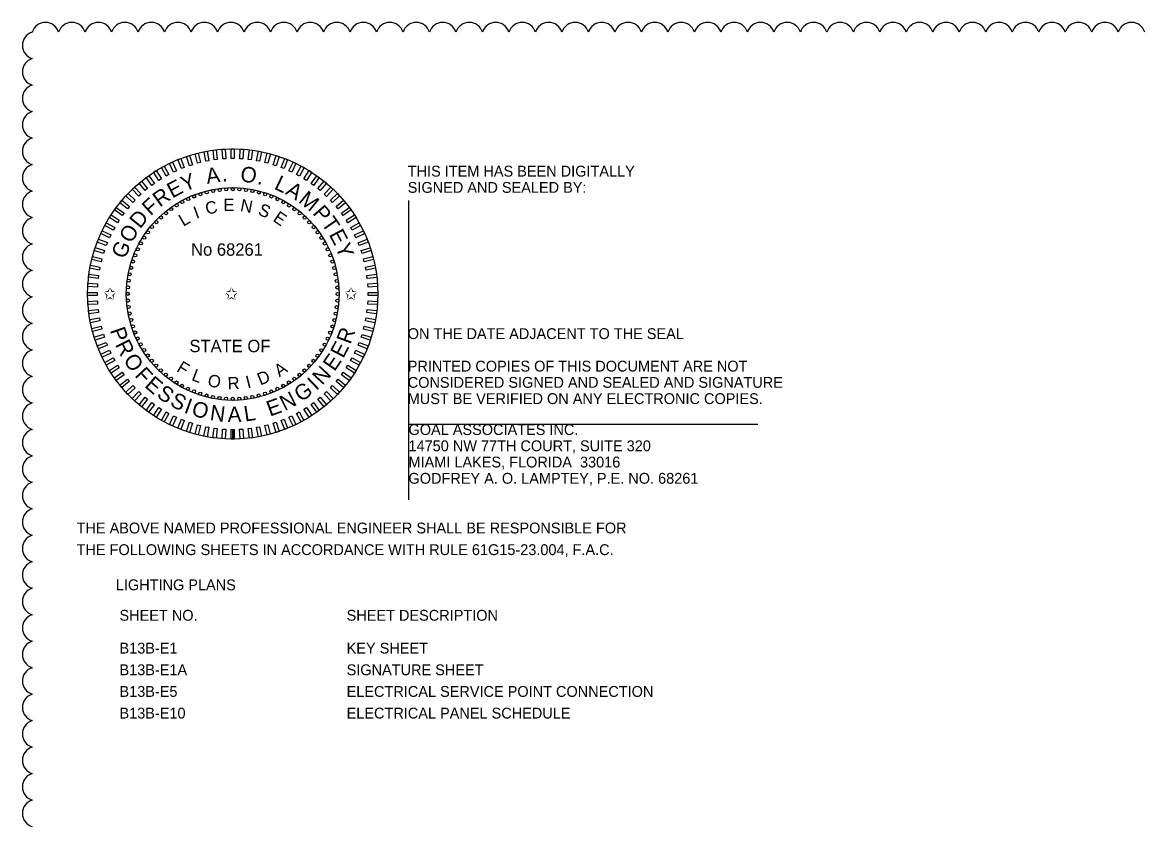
# Model space of a CAD drawing. Extents: x -811.3 to -795.2, y -2199.5 to -2188.9.
# Drawn here: x -810.85 to -803.6, y -2194.13 to -2188.94 of the extents above; entities that cross this region are included whole.
import ezdxf

# ---------------------------------------------------------------- set-up
doc = ezdxf.new("R2010")
doc.units = 0
for name, color, linetype in [('PlotBorder_dp', 7, 'Continuous'), ('ScratchEle_dp', 7, 'Continuous'), ('SheetBorder_dp', 7, 'Continuous'), ('SheetLines_dp', 7, 'Continuous'), ('TextMinor', 7, 'Continuous'), ('TextMisc', 7, 'Continuous')]:
    doc.layers.add(name, color=color, linetype=linetype)

msp = doc.modelspace()

# ---------------------------------------------------------------- linework, layer by layer
at = {"layer": 'PlotBorder_dp'}
for p, q in [((-809.5001, -2191.6301), (-809.5003, -2191.5676)), ((-809.4901, -2191.6301), (-809.4903, -2191.5676)), ((-809.4801, -2191.6301), (-809.4803, -2191.5676))]:
    msp.add_line(p, q, dxfattribs=at)
for points in [[(-809.7508, -2189.8572), (-809.77, -2189.8635), (-809.7893, -2189.8041), (-809.7701, -2189.7979)], [(-809.6979, -2189.8425), (-809.7174, -2189.8475), (-809.7329, -2189.7871), (-809.7134, -2189.782)], [(-809.6441, -2189.8312), (-809.6639, -2189.8349), (-809.6756, -2189.7736), (-809.6558, -2189.7698)], [(-809.5897, -2189.8232), (-809.6097, -2189.8257), (-809.6175, -2189.7638), (-809.5975, -2189.7612)], [(-809.5349, -2189.8187), (-809.555, -2189.8199), (-809.559, -2189.7576), (-809.5388, -2189.7563)], [(-809.4799, -2189.8176), (-809.5001, -2189.8176), (-809.5001, -2189.7551), (-809.4799, -2189.7551)], [(-809.425, -2189.8199), (-809.4452, -2189.8187), (-809.4412, -2189.7563), (-809.4211, -2189.7576)], [(-809.3703, -2189.8257), (-809.3904, -2189.8232), (-809.3825, -2189.7613), (-809.3625, -2189.7638)], [(-809.3162, -2189.835), (-809.336, -2189.8312), (-809.3243, -2189.7699), (-809.3045, -2189.7736)], [(-809.2626, -2189.8476), (-809.2822, -2189.8426), (-809.2667, -2189.7821), (-809.2471, -2189.7871)], [(-809.21, -2189.8635), (-809.2292, -2189.8573), (-809.2099, -2189.7979), (-809.1907, -2189.8042)], [(-809.9027, -2189.9209), (-809.9204, -2189.9306), (-809.9505, -2189.8759), (-809.9328, -2189.8662)], [(-809.8535, -2189.8965), (-809.8717, -2189.9051), (-809.8983, -2189.8486), (-809.8801, -2189.84)], [(-809.8028, -2189.8753), (-809.8215, -2189.8827), (-809.8445, -2189.8246), (-809.8258, -2189.8172)], [(-809.1585, -2189.8828), (-809.1773, -2189.8753), (-809.1543, -2189.8173), (-809.1355, -2189.8247)], [(-809.1083, -2189.9052), (-809.1266, -2189.8966), (-809.1, -2189.8401), (-809.0817, -2189.8487)], [(-809.0596, -2189.9307), (-809.0773, -2189.921), (-809.0473, -2189.8663), (-809.0296, -2189.876)], [(-809.9962, -2189.9787), (-810.0125, -2189.9906), (-810.0492, -2189.94), (-810.0329, -2189.9282)], [(-809.9504, -2189.9483), (-809.9674, -2189.9591), (-810.0009, -2189.9064), (-809.9838, -2189.8956)], [(-809.0127, -2189.9592), (-809.0297, -2189.9484), (-808.9962, -2189.8957), (-808.9792, -2189.9065)], [(-808.9676, -2189.9907), (-808.9839, -2189.9788), (-808.9472, -2189.9283), (-808.9308, -2189.9402)], [(-810.0817, -2190.0478), (-810.0964, -2190.0616), (-810.1392, -2190.0161), (-810.1244, -2190.0022)], [(-810.04, -2190.0119), (-810.0556, -2190.0247), (-810.0954, -2189.9766), (-810.0798, -2189.9638)], [(-808.9245, -2190.0249), (-808.9401, -2190.012), (-808.9003, -2189.9639), (-808.8847, -2189.9768)], [(-808.8837, -2190.0617), (-808.8984, -2190.0479), (-808.8557, -2190.0024), (-808.841, -2190.0162)], [(-810.1579, -2190.127), (-810.1707, -2190.1425), (-810.2188, -2190.1027), (-810.206, -2190.0872)], [(-810.121, -2190.0862), (-810.1348, -2190.1009), (-810.1804, -2190.0581), (-810.1665, -2190.0434)], [(-808.8453, -2190.101), (-808.8591, -2190.0863), (-808.8136, -2190.0436), (-808.7998, -2190.0583)], [(-808.8094, -2190.1427), (-808.8223, -2190.1271), (-808.7742, -2190.0873), (-808.7613, -2190.1029)], [(-810.192, -2190.17), (-810.2039, -2190.1864), (-810.2544, -2190.1497), (-810.2426, -2190.1333)], [(-808.7762, -2190.1865), (-808.7881, -2190.1702), (-808.7376, -2190.1335), (-808.7257, -2190.1498)], [(-810.252, -2190.2621), (-810.2617, -2190.2798), (-810.3164, -2190.2497), (-810.3067, -2190.232)], [(-810.2235, -2190.2151), (-810.2343, -2190.2322), (-810.287, -2190.1987), (-810.2762, -2190.1817)], [(-808.7459, -2190.2323), (-808.7567, -2190.2153), (-808.7039, -2190.1818), (-808.6931, -2190.1989)], [(-808.7184, -2190.28), (-808.7281, -2190.2623), (-808.6734, -2190.2322), (-808.6637, -2190.2499)], [(-810.2775, -2190.3108), (-810.2861, -2190.3291), (-810.3426, -2190.3025), (-810.334, -2190.2842)], [(-808.694, -2190.3292), (-808.7026, -2190.311), (-808.6461, -2190.2844), (-808.6375, -2190.3027)], [(-810.3, -2190.361), (-810.3074, -2190.3798), (-810.3654, -2190.3568), (-810.358, -2190.338)], [(-808.6728, -2190.3799), (-808.6802, -2190.3612), (-808.6222, -2190.3382), (-808.6147, -2190.357)], [(-810.3351, -2190.4651), (-810.3401, -2190.4847), (-810.4006, -2190.4691), (-810.3956, -2190.4496)], [(-810.3192, -2190.4125), (-810.3254, -2190.4317), (-810.3848, -2190.4124), (-810.3786, -2190.3932)], [(-808.6548, -2190.4319), (-808.661, -2190.4127), (-808.6016, -2190.3934), (-808.5954, -2190.4126)], [(-808.64, -2190.4849), (-808.6451, -2190.4653), (-808.5846, -2190.4498), (-808.5796, -2190.4693)], [(-810.3477, -2190.5186), (-810.3515, -2190.5385), (-810.4129, -2190.5268), (-810.4091, -2190.5069)], [(-808.6287, -2190.5386), (-808.6325, -2190.5188), (-808.5711, -2190.5071), (-808.5673, -2190.5269)], [(-810.357, -2190.5728), (-810.3595, -2190.5928), (-810.4215, -2190.585), (-810.4189, -2190.565)], [(-808.6207, -2190.593), (-808.6232, -2190.573), (-808.5613, -2190.5652), (-808.5588, -2190.5852)], [(-810.3628, -2190.6275), (-810.3641, -2190.6476), (-810.4264, -2190.6437), (-810.4251, -2190.6236)], [(-808.6162, -2190.6478), (-808.6174, -2190.6277), (-808.5551, -2190.6238), (-808.5539, -2190.6439)], [(-810.3652, -2190.6824), (-810.3652, -2190.7026), (-810.4276, -2190.7026), (-810.4276, -2190.6824)], [(-810.3641, -2190.7374), (-810.3628, -2190.7575), (-810.4251, -2190.7614), (-810.4264, -2190.7413)], [(-808.6175, -2190.7577), (-808.6162, -2190.7376), (-808.5539, -2190.7415), (-808.5551, -2190.7616)], [(-808.6151, -2190.7028), (-808.6151, -2190.6826), (-808.5527, -2190.6826), (-808.5527, -2190.7028)], [(-810.3595, -2190.7922), (-810.357, -2190.8122), (-810.4189, -2190.82), (-810.4215, -2190.8)], [(-808.6233, -2190.8124), (-808.6207, -2190.7923), (-808.5588, -2190.8002), (-808.5613, -2190.8202)], [(-810.3516, -2190.8466), (-810.3478, -2190.8664), (-810.4091, -2190.8781), (-810.4129, -2190.8583)], [(-808.6325, -2190.8666), (-808.6287, -2190.8467), (-808.5674, -2190.8584), (-808.5712, -2190.8783)], [(-810.3402, -2190.9003), (-810.3352, -2190.9199), (-810.3957, -2190.9354), (-810.4007, -2190.9159)], [(-810.3255, -2190.9533), (-810.3192, -2190.9725), (-810.3786, -2190.9918), (-810.3849, -2190.9726)], [(-808.6611, -2190.9727), (-808.6548, -2190.9535), (-808.5954, -2190.9728), (-808.6017, -2190.992)], [(-808.6451, -2190.9201), (-808.6401, -2190.9005), (-808.5796, -2190.916), (-808.5846, -2190.9356)], [(-810.3075, -2191.0052), (-810.3, -2191.024), (-810.3581, -2191.047), (-810.3655, -2191.0282)], [(-808.6803, -2191.0242), (-808.6729, -2191.0054), (-808.6148, -2191.0284), (-808.6222, -2191.0472)], [(-810.2862, -2191.0559), (-810.2776, -2191.0742), (-810.3341, -2191.1008), (-810.3427, -2191.0825)], [(-810.2618, -2191.1052), (-810.2521, -2191.1229), (-810.3068, -2191.153), (-810.3165, -2191.1353)], [(-808.7282, -2191.1231), (-808.7185, -2191.1054), (-808.6638, -2191.1355), (-808.6735, -2191.1532)], [(-808.7027, -2191.0744), (-808.6941, -2191.0561), (-808.6376, -2191.0827), (-808.6462, -2191.101)], [(-810.2344, -2191.1529), (-810.2236, -2191.1699), (-810.2763, -2191.2034), (-810.2871, -2191.1863)], [(-808.7568, -2191.1701), (-808.746, -2191.153), (-808.6932, -2191.1865), (-808.704, -2191.2035)], [(-810.204, -2191.1987), (-810.1922, -2191.215), (-810.2427, -2191.2517), (-810.2545, -2191.2354)], [(-810.1708, -2191.2425), (-810.158, -2191.2581), (-810.2061, -2191.2979), (-810.2189, -2191.2823)], [(-808.8224, -2191.2582), (-808.8095, -2191.2427), (-808.7614, -2191.2825), (-808.7743, -2191.298)], [(-808.7882, -2191.2152), (-808.7763, -2191.1988), (-808.7258, -2191.2355), (-808.7377, -2191.2519)], [(-810.135, -2191.2842), (-810.1211, -2191.2989), (-810.1667, -2191.3416), (-810.1805, -2191.3269)], [(-810.0965, -2191.3235), (-810.0818, -2191.3373), (-810.1246, -2191.3828), (-810.1393, -2191.369)], [(-808.8985, -2191.3374), (-808.8838, -2191.3236), (-808.8411, -2191.3691), (-808.8558, -2191.383)], [(-808.8592, -2191.299), (-808.8454, -2191.2843), (-808.7999, -2191.327), (-808.8137, -2191.3418)], [(-810.0557, -2191.3603), (-810.0402, -2191.3732), (-810.08, -2191.4213), (-810.0955, -2191.4084)], [(-810.0127, -2191.3945), (-809.9964, -2191.4064), (-810.0331, -2191.4569), (-810.0494, -2191.445)], [(-808.984, -2191.4065), (-808.9677, -2191.3946), (-808.931, -2191.4451), (-808.9473, -2191.457)], [(-808.9402, -2191.3733), (-808.9247, -2191.3604), (-808.8848, -2191.4086), (-808.9004, -2191.4214)], [(-809.9676, -2191.426), (-809.9505, -2191.4368), (-809.984, -2191.4895), (-810.001, -2191.4787)], [(-809.9206, -2191.4545), (-809.9029, -2191.4642), (-809.933, -2191.5189), (-809.9507, -2191.5092)], [(-809.0775, -2191.4643), (-809.0598, -2191.4546), (-809.0297, -2191.5093), (-809.0474, -2191.519)], [(-809.0299, -2191.4369), (-809.0128, -2191.4261), (-808.9794, -2191.4788), (-808.9964, -2191.4896)], [(-809.8719, -2191.48), (-809.8536, -2191.4886), (-809.8802, -2191.5451), (-809.8985, -2191.5365)], [(-809.8217, -2191.5024), (-809.8029, -2191.5099), (-809.8259, -2191.5679), (-809.8447, -2191.5605)], [(-809.7702, -2191.5217), (-809.751, -2191.5279), (-809.7703, -2191.5873), (-809.7895, -2191.581)], [(-809.7176, -2191.5376), (-809.698, -2191.5426), (-809.7136, -2191.6031), (-809.7331, -2191.5981)], [(-809.2824, -2191.5427), (-809.2628, -2191.5376), (-809.2473, -2191.5981), (-809.2668, -2191.6031)], [(-809.2294, -2191.5279), (-809.2102, -2191.5217), (-809.1909, -2191.5811), (-809.2101, -2191.5873)], [(-809.1775, -2191.5099), (-809.1587, -2191.5025), (-809.1357, -2191.5606), (-809.1545, -2191.568)], [(-809.1268, -2191.4887), (-809.1085, -2191.4801), (-809.0819, -2191.5366), (-809.1002, -2191.5452)], [(-809.6641, -2191.5502), (-809.6443, -2191.554), (-809.656, -2191.6153), (-809.6758, -2191.6116)], [(-809.6099, -2191.5594), (-809.5899, -2191.562), (-809.5977, -2191.6239), (-809.6177, -2191.6214)], [(-809.5552, -2191.5653), (-809.5351, -2191.5665), (-809.539, -2191.6288), (-809.5592, -2191.6276)], [(-809.5003, -2191.5676), (-809.4801, -2191.5676), (-809.4801, -2191.6301), (-809.5003, -2191.6301)], [(-809.4453, -2191.5665), (-809.4252, -2191.5653), (-809.4213, -2191.6276), (-809.4414, -2191.6289)], [(-809.3906, -2191.562), (-809.3705, -2191.5595), (-809.3627, -2191.6214), (-809.3827, -2191.624)], [(-809.3362, -2191.554), (-809.3163, -2191.5503), (-809.3046, -2191.6116), (-809.3245, -2191.6154)]]:
    msp.add_lwpolyline(points, close=True, dxfattribs=at)
for centre in [(-809.6165, -2190.027), (-809.5745, -2190.0204), (-809.5321, -2190.0164), (-809.4896, -2190.0151), (-809.447, -2190.0165), (-809.4047, -2190.0205), (-809.3626, -2190.0272), (-809.816, -2190.0987), (-809.7781, -2190.0794), (-809.739, -2190.0625), (-809.6989, -2190.0481), (-809.6581, -2190.0363), (-809.3211, -2190.0366), (-809.2802, -2190.0485), (-809.2402, -2190.0629), (-809.2012, -2190.0798), (-809.1633, -2190.0992), (-809.9215, -2190.1702), (-809.8879, -2190.1442), (-809.8527, -2190.1203), (-809.1266, -2190.1209), (-809.0915, -2190.1448), (-809.0579, -2190.171), (-809.9836, -2190.2284), (-809.9535, -2190.1984), (-809.026, -2190.1991), (-808.9959, -2190.2292), (-810.0379, -2190.2939), (-810.0118, -2190.2603), (-808.9678, -2190.2612), (-808.9417, -2190.2948), (-810.0835, -2190.3657), (-810.0618, -2190.3291), (-808.9178, -2190.3301), (-808.8962, -2190.3667), (-810.1198, -2190.4427), (-810.1029, -2190.4036), (-808.8769, -2190.4047), (-808.86, -2190.4437), (-810.1462, -2190.5236), (-810.1343, -2190.4827), (-808.8456, -2190.4838), (-808.8338, -2190.5247), (-810.1622, -2190.6071), (-810.1555, -2190.5651), (-808.8245, -2190.5662), (-808.8179, -2190.6082), (-810.1662, -2190.6495), (-808.814, -2190.6506), (-810.1676, -2190.692), (-810.1663, -2190.7346), (-808.814, -2190.7357), (-808.8127, -2190.6932), (-810.1623, -2190.7769), (-810.1557, -2190.819), (-808.8248, -2190.8201), (-808.8181, -2190.7781), (-810.1464, -2190.8605), (-810.1346, -2190.9014), (-808.846, -2190.9025), (-808.8341, -2190.8616), (-810.1202, -2190.9415), (-808.8604, -2190.9425), (-810.1034, -2190.9805), (-810.0841, -2191.0185), (-808.8967, -2191.0195), (-808.8774, -2190.9816), (-810.0624, -2191.0551), (-810.0385, -2191.0903), (-808.9424, -2191.0913), (-808.9184, -2191.0561), (-810.0125, -2191.124), (-809.9844, -2191.1559), (-809.9543, -2191.1861), (-809.0268, -2191.1868), (-808.9967, -2191.1568), (-808.9685, -2191.1249), (-809.9224, -2191.2142), (-809.8888, -2191.2403), (-809.8536, -2191.2643), (-809.1276, -2191.2649), (-809.0924, -2191.241), (-809.0587, -2191.215), (-809.817, -2191.286), (-809.7791, -2191.3053), (-809.74, -2191.3223), (-809.7, -2191.3367), (-809.2813, -2191.3371), (-809.2413, -2191.3227), (-809.2022, -2191.3058), (-809.1642, -2191.2865), (-809.6591, -2191.3486), (-809.6176, -2191.358), (-809.5756, -2191.3647), (-809.5332, -2191.3687), (-809.4901, -2191.3701), (-809.4481, -2191.3688), (-809.4058, -2191.3648), (-809.3637, -2191.3582), (-809.3222, -2191.3489)]:
    msp.add_circle(centre, 0.01, dxfattribs=at)
at = {"layer": 'ScratchEle_dp'}
for centre, start, end in [((-810.7588, -2189.0862), 107.5, 252.5), ((-810.7002, -2189.0276), 17.5, 162.5), ((-810.5291, -2189.0276), 17.5, 162.5), ((-810.358, -2189.0276), 17.5, 162.5), ((-810.1868, -2189.0276), 17.5, 162.5), ((-810.0157, -2189.0276), 17.5, 162.5), ((-809.8446, -2189.0276), 17.5, 162.5), ((-809.6735, -2189.0276), 17.5, 162.5), ((-809.5024, -2189.0276), 17.5, 162.5), ((-809.3312, -2189.0276), 17.5, 162.5), ((-809.1601, -2189.0276), 17.5, 162.5), ((-808.989, -2189.0276), 17.5, 162.5), ((-808.8179, -2189.0276), 17.5, 162.5), ((-808.6467, -2189.0276), 17.5, 162.5), ((-808.4756, -2189.0276), 17.5, 162.5), ((-808.3045, -2189.0276), 17.5, 162.5), ((-808.1334, -2189.0276), 17.5, 162.5), ((-807.9622, -2189.0276), 17.5, 162.5), ((-807.7911, -2189.0276), 17.5, 162.5), ((-807.62, -2189.0276), 17.5, 162.5), ((-807.4489, -2189.0276), 17.5, 162.5), ((-807.2778, -2189.0276), 17.5, 162.5), ((-807.1066, -2189.0276), 17.5, 162.5), ((-806.9355, -2189.0276), 17.5, 162.5), ((-806.7644, -2189.0276), 17.5, 162.5), ((-806.5933, -2189.0276), 17.5, 162.5), ((-806.4221, -2189.0276), 17.5, 162.5), ((-806.251, -2189.0276), 17.5, 162.5), ((-806.0799, -2189.0276), 17.5, 162.5), ((-805.9088, -2189.0276), 17.5, 162.5), ((-805.7377, -2189.0276), 17.5, 162.5), ((-805.5665, -2189.0276), 17.5, 162.5), ((-805.3954, -2189.0276), 17.5, 162.5), ((-805.2243, -2189.0276), 17.5, 162.5), ((-805.0532, -2189.0276), 17.5, 162.5), ((-804.882, -2189.0276), 17.5, 162.5), ((-804.7109, -2189.0276), 17.5, 162.5), ((-804.5398, -2189.0276), 17.5, 162.5), ((-804.3687, -2189.0276), 17.5, 162.5), ((-804.1976, -2189.0276), 17.5, 162.5), ((-804.0264, -2189.0276), 17.5, 162.5), ((-803.8553, -2189.0276), 17.5, 162.5), ((-803.6842, -2189.0276), 17.5, 162.5), ((-810.7588, -2189.2573), 107.5, 252.5), ((-810.7588, -2189.4284), 107.5, 252.5), ((-810.7588, -2189.5996), 107.5, 252.5), ((-810.7588, -2189.7707), 107.5, 252.5), ((-810.7588, -2189.9418), 107.5, 252.5), ((-810.7588, -2190.1129), 107.5, 252.5), ((-810.7588, -2190.2841), 107.5, 252.5), ((-810.7588, -2190.4552), 107.5, 252.5), ((-810.7588, -2190.6263), 107.5, 252.5), ((-810.7588, -2190.7974), 107.5, 252.5), ((-810.7588, -2190.9685), 107.5, 252.5), ((-810.7588, -2191.1397), 107.5, 252.5), ((-810.7588, -2191.3108), 107.5, 252.5), ((-810.7588, -2191.4819), 107.5, 252.5), ((-810.7588, -2191.653), 107.5, 252.5), ((-810.7588, -2191.8242), 107.5, 252.5), ((-810.7588, -2191.9953), 107.5, 252.5), ((-810.7588, -2192.1664), 107.5, 252.5), ((-810.7588, -2192.3375), 107.5, 252.5), ((-810.7588, -2192.5087), 107.5, 252.5), ((-810.7588, -2192.6798), 107.5, 252.5), ((-810.7588, -2192.8509), 107.5, 252.5), ((-810.7588, -2193.022), 107.5, 252.5), ((-810.7588, -2193.1931), 107.5, 252.5), ((-810.7588, -2193.3643), 107.5, 252.5), ((-810.7588, -2193.5354), 107.5, 252.5), ((-810.7588, -2193.7065), 107.5, 252.5), ((-810.7588, -2193.8776), 107.5, 252.5), ((-810.7588, -2194.0488), 107.5, 252.5)]:
    msp.add_arc(centre, 0.0897, start, end, dxfattribs=at)
at = {"layer": 'SheetLines_dp'}
for radius in [0.9375, 0.6875]:
    msp.add_circle((-809.4901, -2190.6926), radius, dxfattribs=at)
at = {"layer": 'TextMisc'}
for p, q in [((-808.3546, -2190.0892), (-808.3546, -2192.0239)), ((-808.3546, -2191.5339), (-806.0979, -2191.5339))]:
    msp.add_line(p, q, dxfattribs=at)

# ---------------------------------------------------------------- texts
at = {"layer": 'PlotBorder_dp'}
for s, height, rotation, p in [('A', 0.1, 8.80884, (-809.6551, -2189.982)), ('O', 0.1, 352.18771, (-809.4449, -2189.9645)), ('E', 0.1, 28.10553, (-809.8806, -2190.0764)), ('Y', 0.1, 21.06329, (-809.8021, -2190.0332)), ('.', 0.1, 1.04184, (-809.5575, -2189.9662)), ('L', 0.1, 334.67271, (-809.2279, -2190.0118)), ('R', 0.1, 35.92688, (-809.9609, -2190.1353)), ('.', 0.1, 343.52684, (-809.3358, -2189.9796)), ('A', 0.1, 328.40959, (-809.1552, -2190.0445)), ('F', 0.1, 42.37723, (-810.0205, -2190.1917)), ('C', 0.08, 12.20255, (-809.6579, -2190.181)), ('E', 0.08, 0.41861, (-809.5498, -2190.1575)), ('N', 0.08, 349.29143, (-809.4455, -2190.1561)), ('M', 0.1, 320.6426, (-809.0707, -2190.0957)), ('D', 0.1, 50.8569, (-810.0886, -2190.2754)), ('I', 0.08, 20.01168, (-809.7258, -2190.2085)), ('S', 0.08, 337.02207, (-809.3325, -2190.1778)), ('E', 0.08, 325.86633, (-809.2358, -2190.218)), ('P', 0.1, 311.19658, (-808.9784, -2190.1727)), ('L', 0.08, 30.40215, (-809.8093, -2190.259)), ('T', 0.1, 304.45632, (-808.9209, -2190.2363)), ('O', 0.1, 59.51777, (-810.1446, -2190.3702)), ('E', 0.1, 297.63152, (-808.8707, -2190.3072)), ('G', 0.1, 68.0518, (-810.1851, -2190.4709)), ('Y', 0.1, 290.58928, (-808.8281, -2190.386)), ('P', 0.1, 289.40551, (-810.2848, -2190.9272)), ('R', 0.1, 69.5134, (-808.7299, -2191.0223)), ('R', 0.1, 296.14576, (-810.2518, -2191.0188)), ('E', 0.1, 62.47116, (-808.7761, -2191.113)), ('O', 0.1, 303.96711, (-810.2003, -2191.1194)), ('E', 0.1, 55.42892, (-808.833, -2191.1974)), ('F', 0.1, 312.62798, (-810.1279, -2191.2215)), ('F', 0.08, 328.72408, (-809.8582, -2191.1892)), ('L', 0.08, 339.29159, (-809.7609, -2191.2483)), ('A', 0.08, 34.49917, (-809.1883, -2191.232)), ('N', 0.1, 47.17876, (-808.9123, -2191.2864)), ('E', 0.1, 319.07833, (-810.0645, -2191.2898)), ('O', 0.08, 349.68206, (-809.6562, -2191.288)), ('R', 0.08, 2.33977, (-809.5217, -2191.3099)), ('I', 0.08, 14.20366, (-809.3941, -2191.3032)), ('D', 0.08, 22.01279, (-809.312, -2191.2845)), ('I', 0.1, 43.64556, (-808.9499, -2191.3209)), ('S', 0.1, 326.12056, (-809.9869, -2191.3557)), ('N', 0.1, 26.86136, (-809.1544, -2191.4501)), ('G', 0.1, 35.11153, (-809.0492, -2191.3941)), ('S', 0.1, 333.193, (-809.9015, -2191.4119)), ('I', 0.1, 340.26543, (-809.8098, -2191.457)), ('O', 0.1, 343.79863, (-809.7621, -2191.4753)), ('E', 0.1, 19.81912, (-809.2498, -2191.4856)), ('N', 0.1, 352.45949, (-809.6411, -2191.5073)), ('A', 0.1, 0.70966, (-809.5227, -2191.5206)), ('L', 0.1, 8.47665, (-809.4105, -2191.5174))]:
    msp.add_text(s, height=height, rotation=rotation, dxfattribs=at).set_placement(p)
for s, p in [('No 68261', (-809.7591, -2190.4454)), ('✩', (-810.3251, -2190.7305)), ('✩', (-809.5404, -2190.7305)), ('✩', (-808.7685, -2190.7305)), ('STATE OF', (-809.7698, -2191.0688))]:
    msp.add_text(s, height=0.08, dxfattribs=at).set_placement(p)
at = {"layer": 'SheetBorder_dp'}
for s, p in [('THIS ITEM HAS BEEN DIGITALLY', (-808.3596, -2189.934)), ('SIGNED AND SEALED BY:', (-808.3596, -2190.039)), ('ON THE DATE ADJACENT TO THE SEAL', (-808.3596, -2190.984)), ('PRINTED COPIES OF THIS DOCUMENT ARE NOT ', (-808.3596, -2191.194)), ('CONSIDERED SIGNED AND SEALED AND SIGNATURE ', (-808.3596, -2191.299)), ('MUST BE VERIFIED ON ANY ELECTRONIC COPIES.', (-808.3596, -2191.404)), ('GOAL ASSOCIATES INC.', (-808.3546, -2191.6039)), ('14750 NW 77TH COURT, SUITE 320', (-808.3546, -2191.7089)), ('MIAMI LAKES, FLORIDA  33016', (-808.3546, -2191.8139)), ('GODFREY A. O. LAMPTEY, P.E. NO. 68261', (-808.3546, -2191.9189)), ('THE ABOVE NAMED PROFESSIONAL ENGINEER SHALL BE RESPONSIBLE FOR ', (-810.4987, -2192.24)), ('THE FOLLOWING SHEETS IN ACCORDANCE WITH RULE 61G15-23.004, F.A.C.', (-810.4987, -2192.38)), ('LIGHTING PLANS', (-810.245, -2192.6071))]:
    msp.add_text(s, height=0.07, dxfattribs=at).set_placement(p)
at = {"layer": 'TextMinor'}
for s, p in [('SHEET NO.', (-810.2215, -2192.8041)), ('SHEET DESCRIPTION', (-808.7542, -2192.8041)), ('B13B-E1', (-810.2215, -2193.0162)), ('KEY SHEET', (-808.7542, -2193.0162)), ('B13B-E1A', (-810.2215, -2193.1562)), ('SIGNATURE SHEET', (-808.7542, -2193.1562)), ('B13B-E5', (-810.2215, -2193.2962)), ('ELECTRICAL SERVICE POINT CONNECTION', (-808.7542, -2193.2962)), ('B13B-E10', (-810.2215, -2193.4362)), ('ELECTRICAL PANEL SCHEDULE', (-808.7542, -2193.4362))]:
    msp.add_text(s, height=0.07, dxfattribs=at).set_placement(p)

doc.saveas('drawing.dxf')
